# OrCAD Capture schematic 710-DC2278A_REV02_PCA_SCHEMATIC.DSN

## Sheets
1 PAGE4
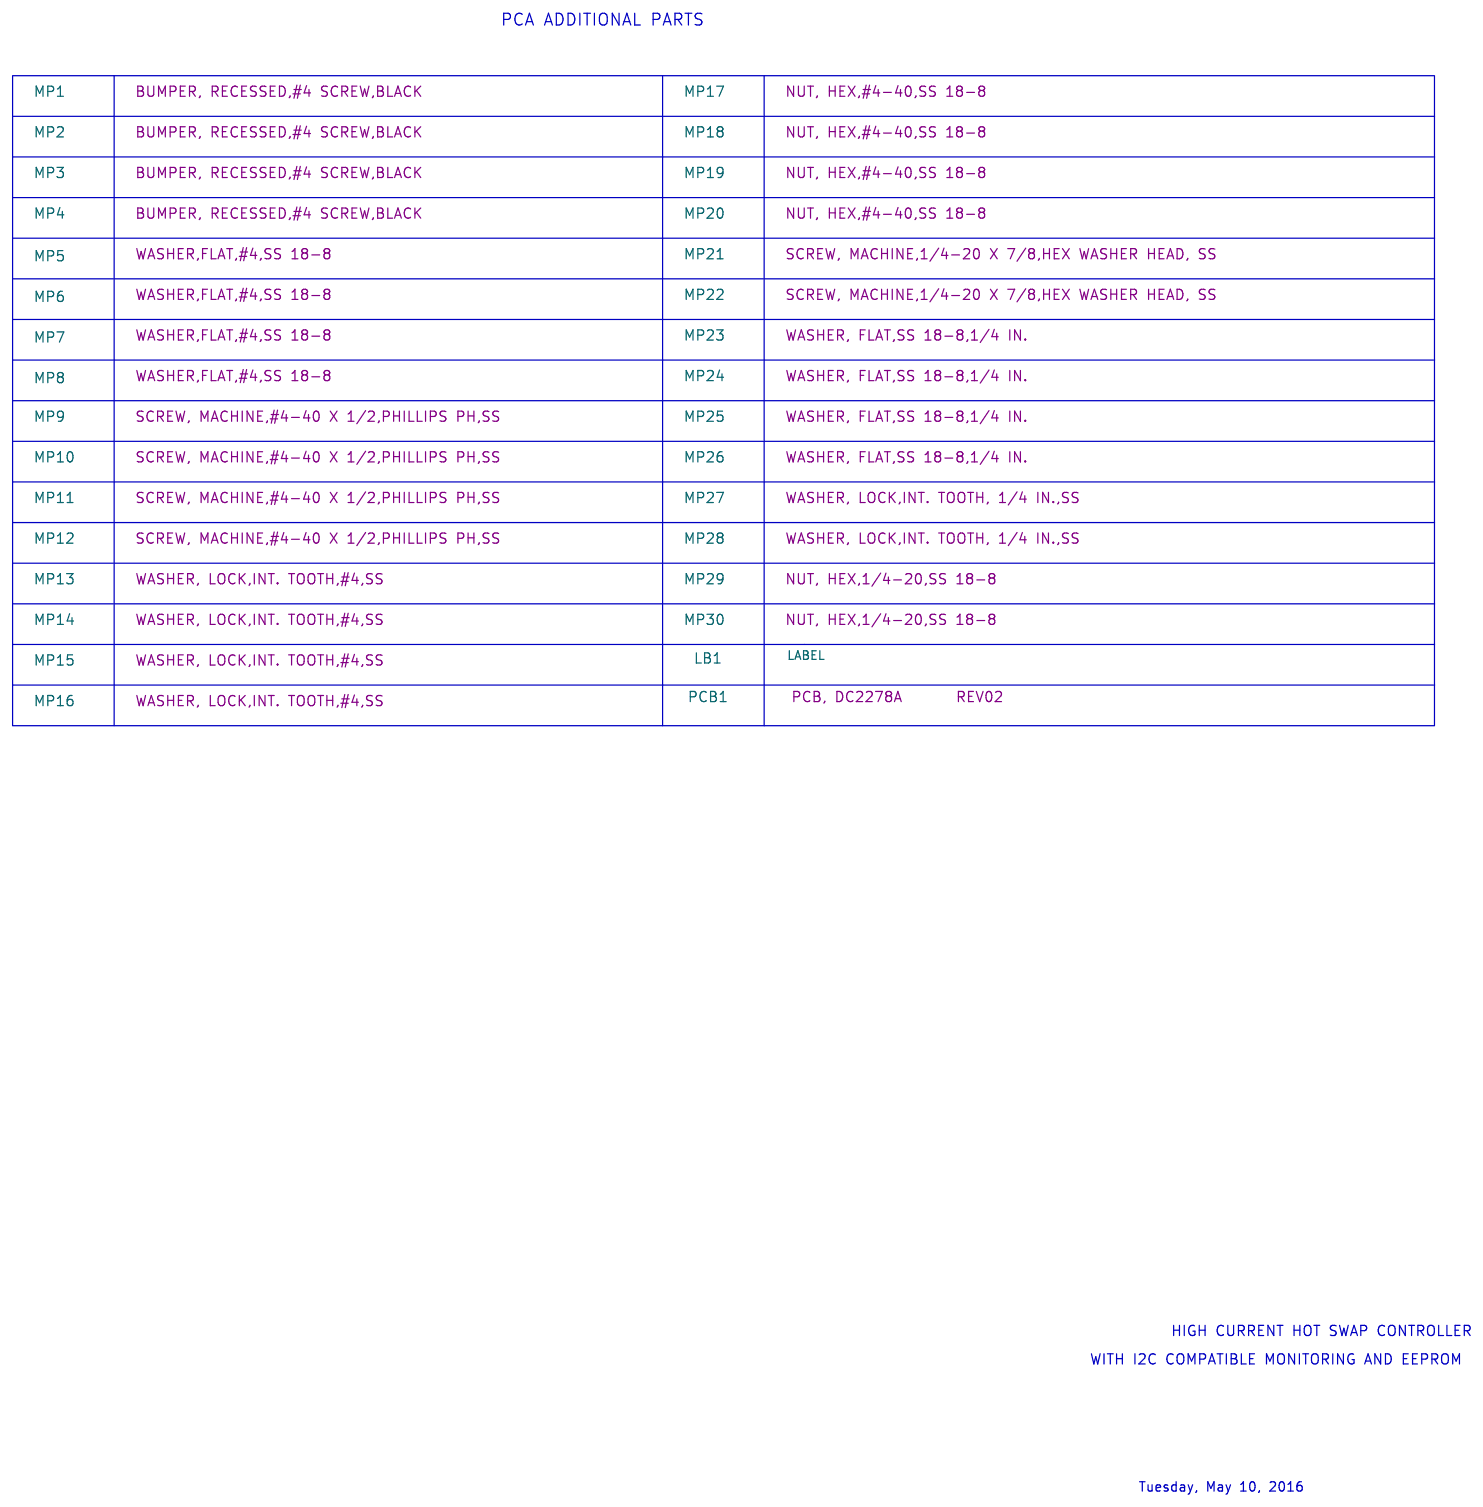
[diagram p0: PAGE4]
2 PAGE1: size Custom; note: HIGH CURRENT HOT SWAP CONTROLLER WITH I2C COMPATIBLE MONITORING AND EEPROM
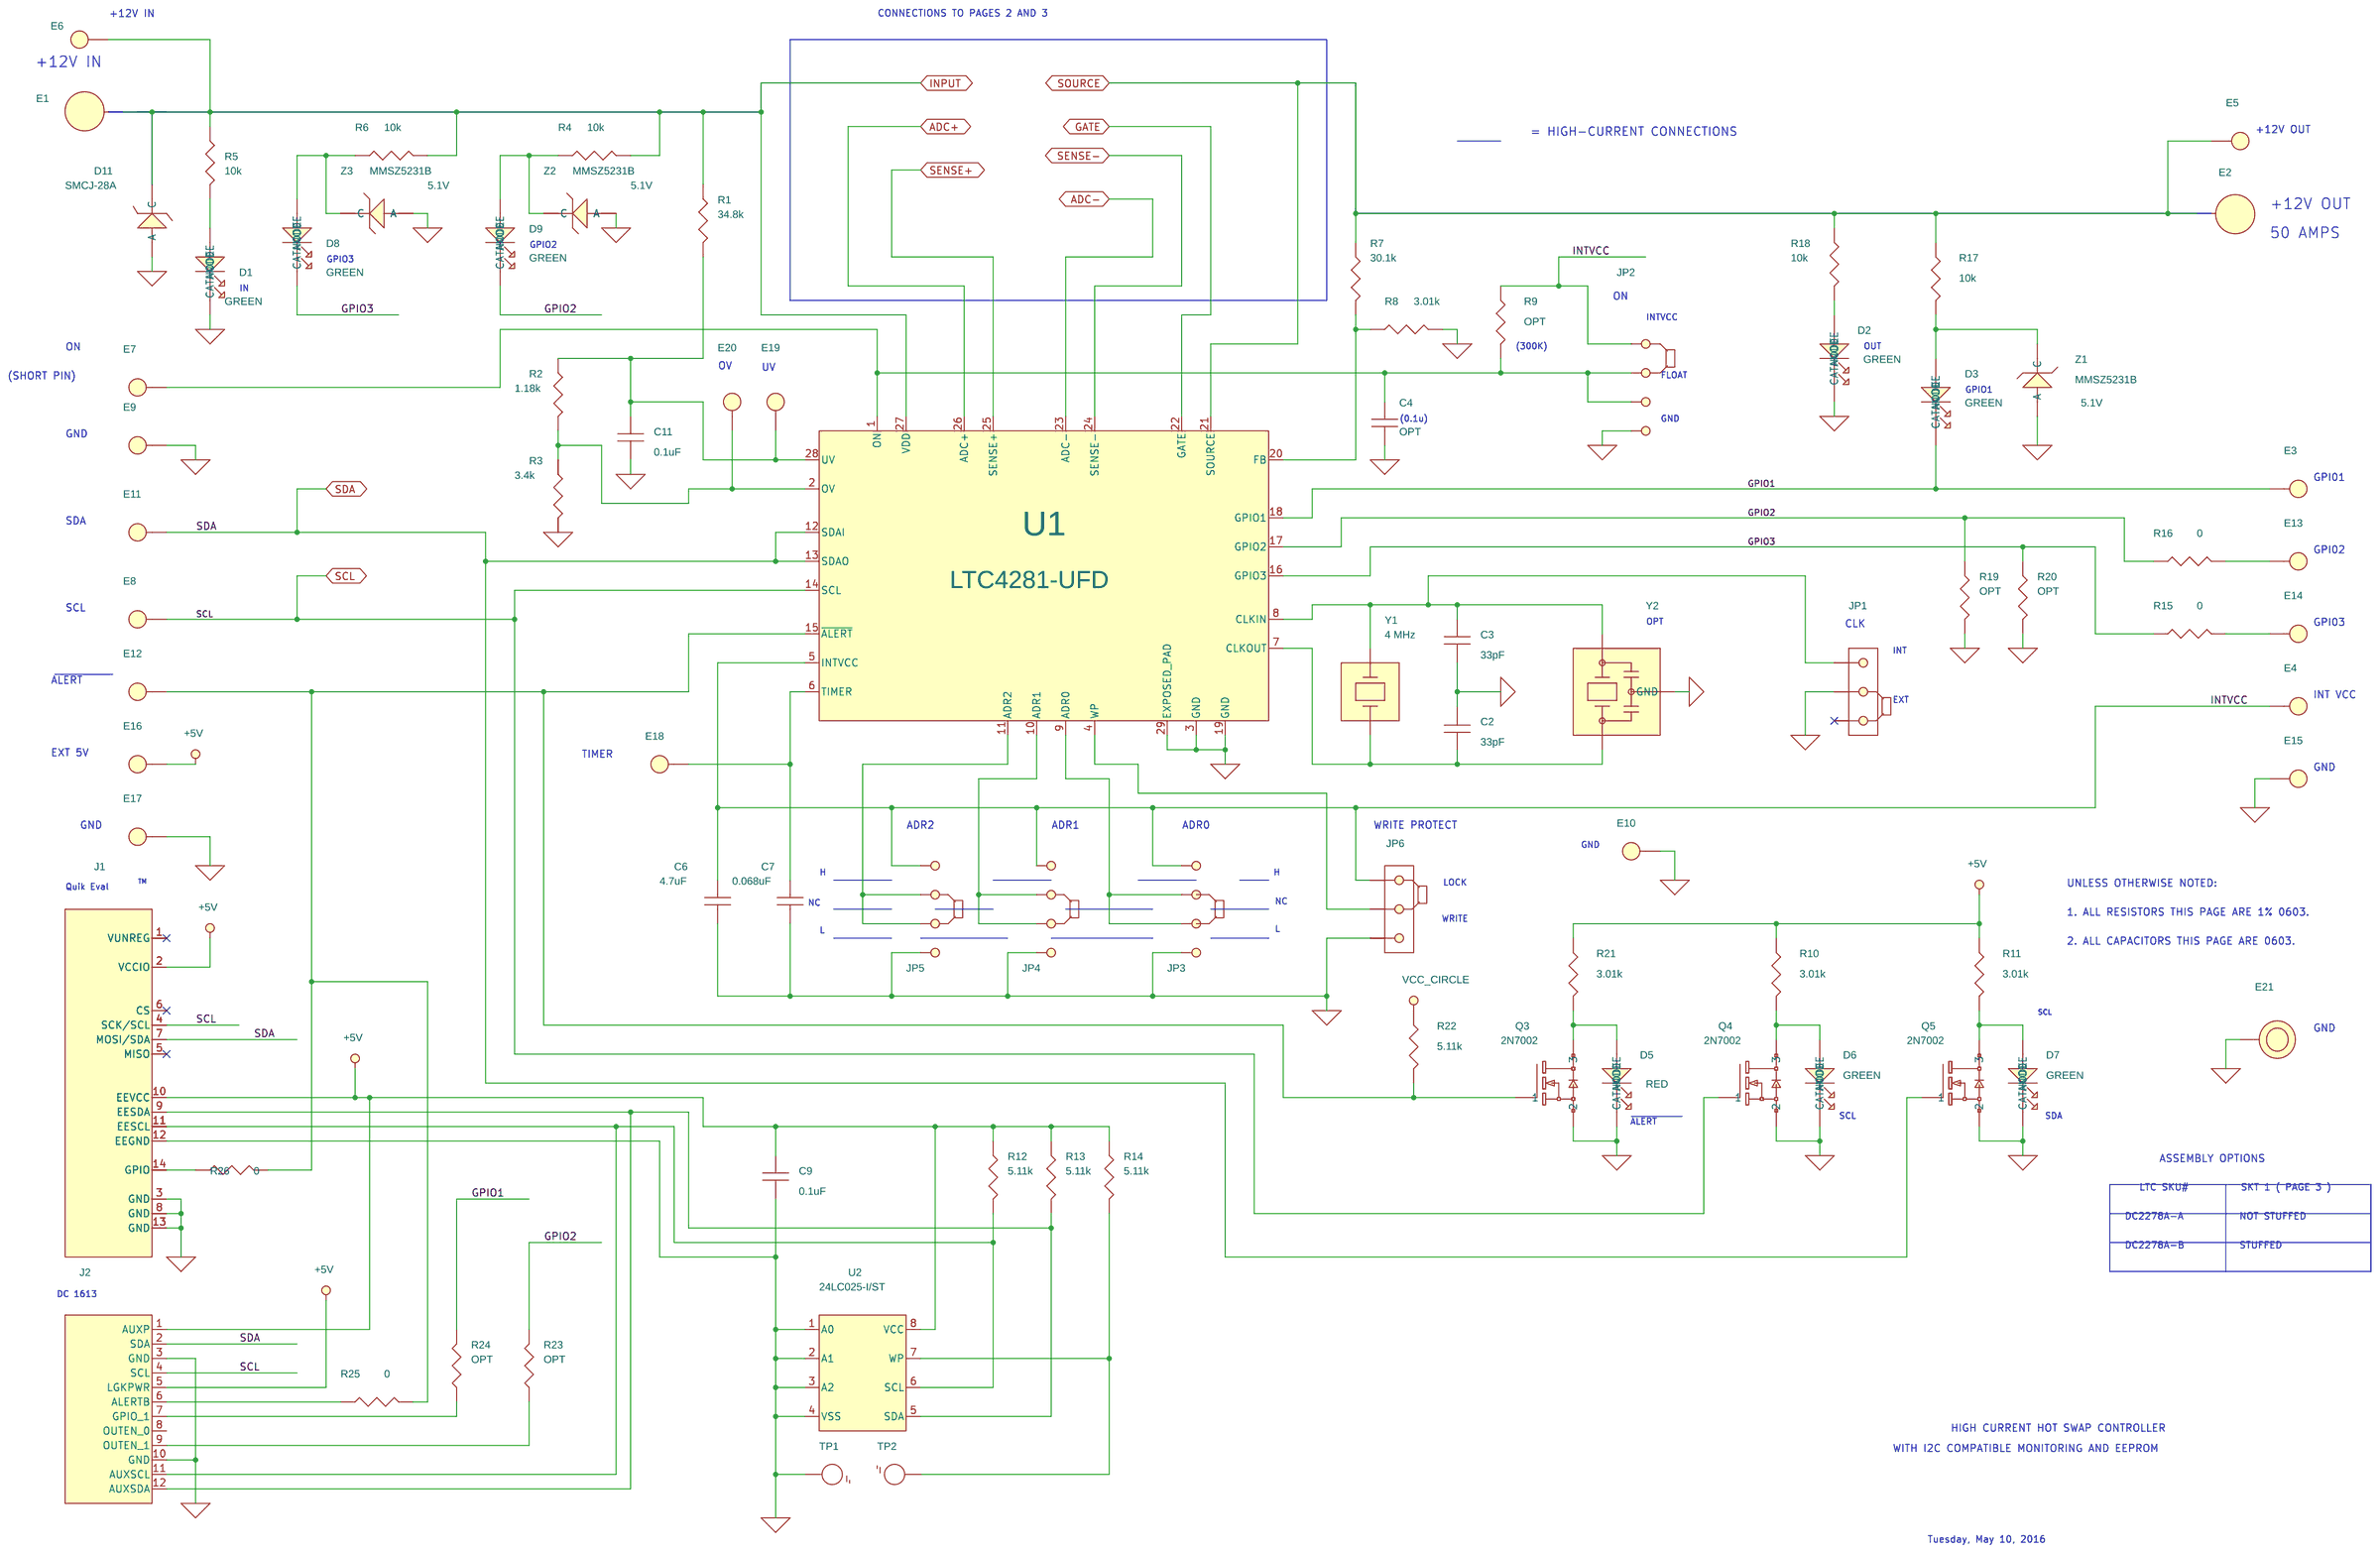
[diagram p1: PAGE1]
3 PAGE2: size Custom
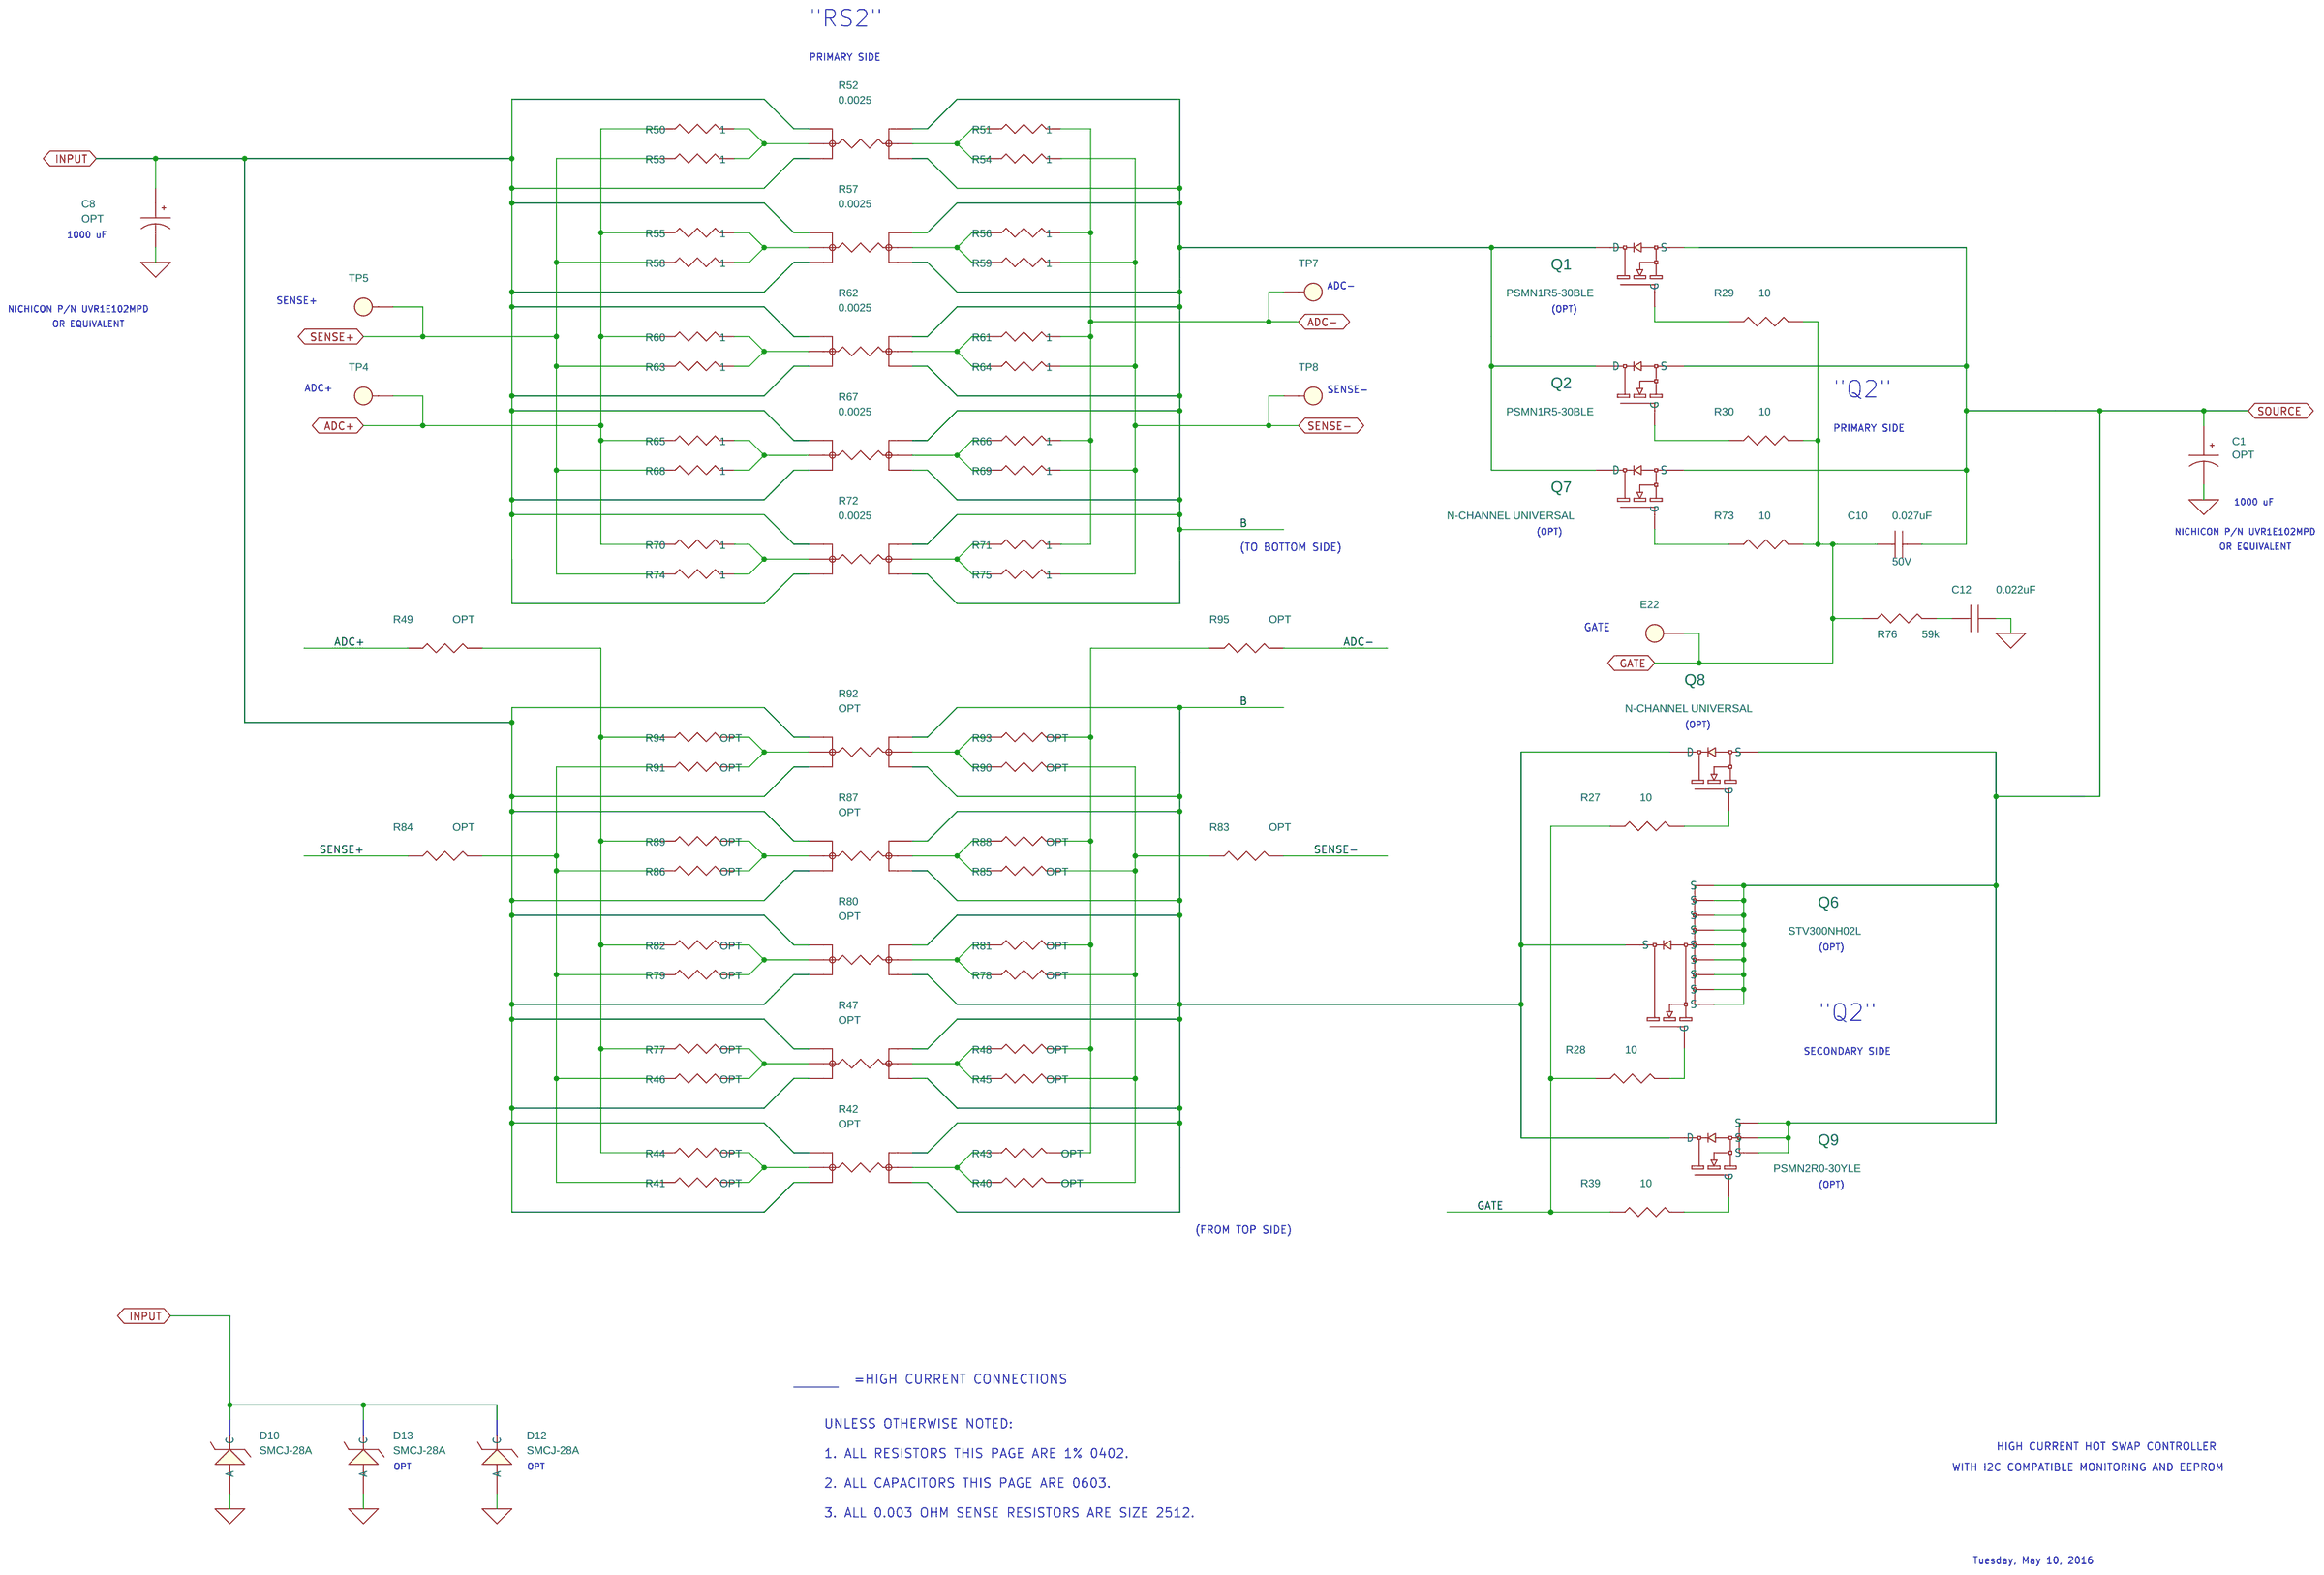
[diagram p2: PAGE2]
4 PAGE3: size Custom
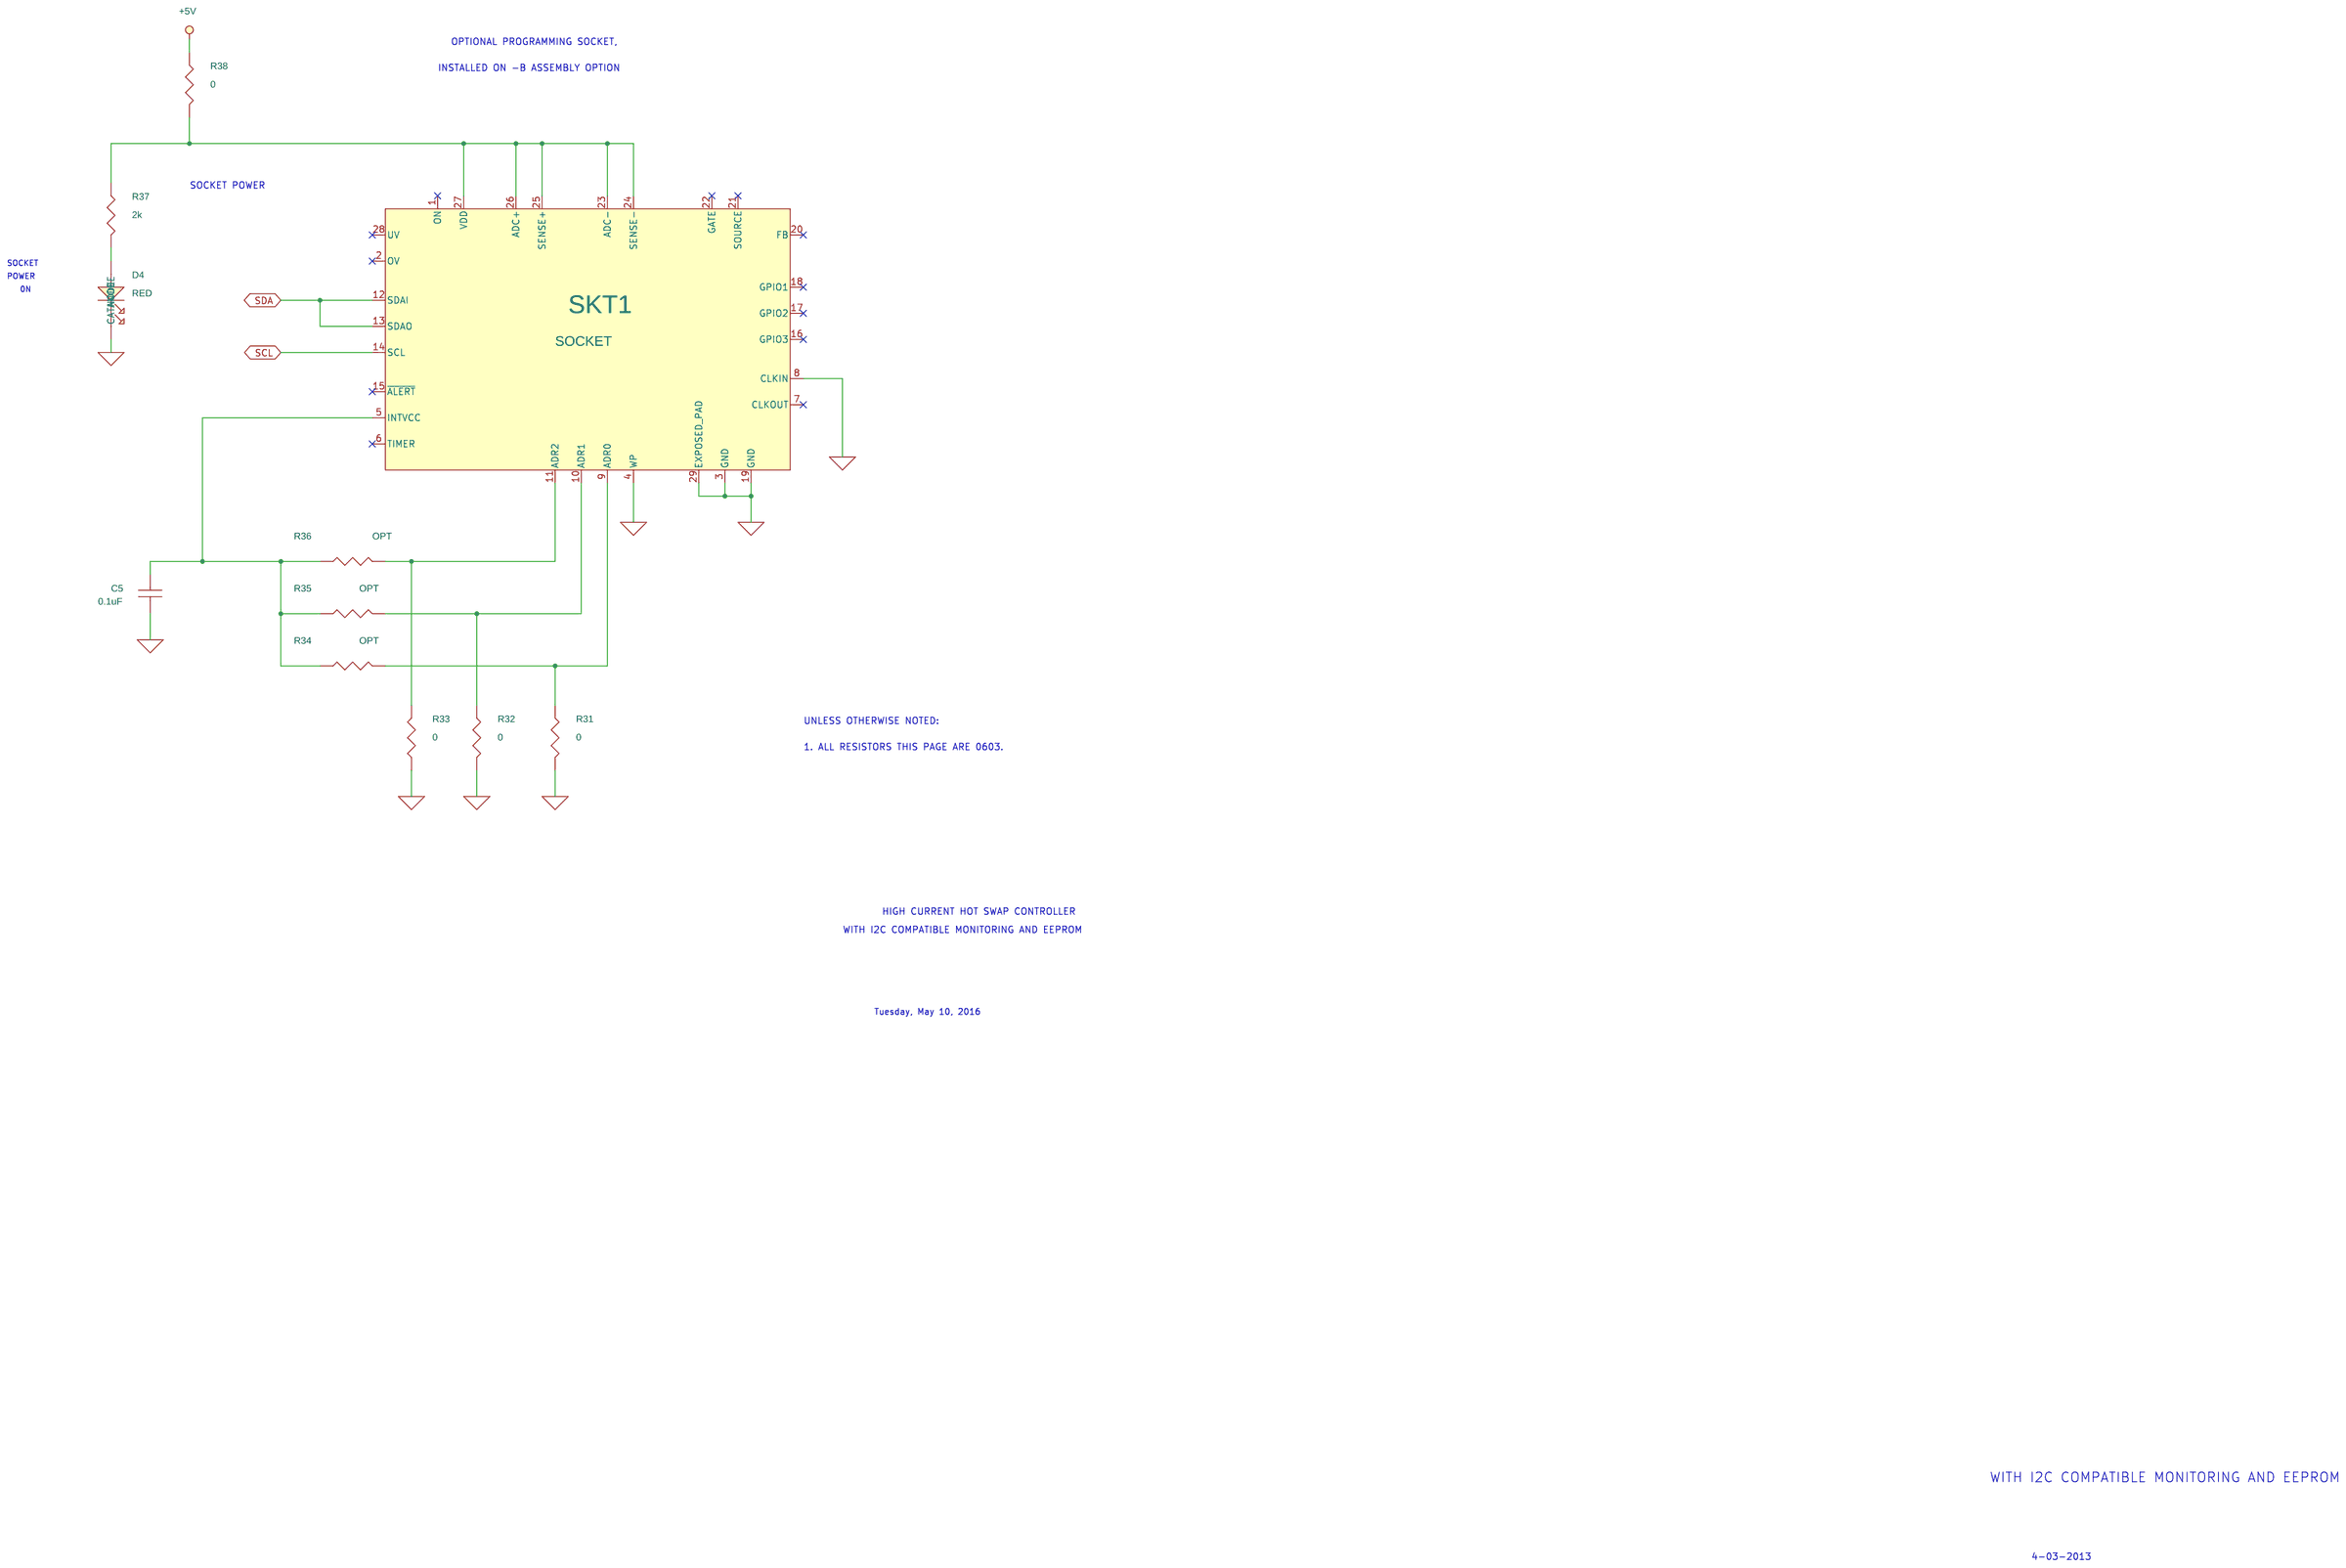
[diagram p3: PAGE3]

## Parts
sheet PAGE1
C2  33pF  [CC0603N]
C3  33pF  [CC0603N]
C4  OPT  [CC0603N]
C6  4.7uF  [CC0603N]
C7  0.068uF  [CC0603N]
C9  0.1uF  [CC0603N]
C11  0.1uF  [CC0603N]
D1  GREEN  [WURTH_LED_0805]
D2  GREEN  [WURTH_LED_0805]
D3  GREEN  [WURTH_LED_0805]
D5  RED  [LED_0805]
D6  GREEN  [WURTH_LED_0805]
D7  GREEN  [WURTH_LED_0805]
D8  GREEN  [WURTH_LED_0805]
D9  GREEN  [WURTH_LED_0805]
D11  SMCJ-28A  [DIODESINC-SMC]
E1  LUG, TONGUE  [CBA70-14-CY]
E2  LUG, TONGUE  [CBA70-14-CY]
E3  TEST POINT  [MILLMAX2308]
E4  TEST POINT  [MILLMAX2308]
E5  TEST POINT  [MILLMAX2308]
E6  TEST POINT  [MILLMAX2308]
E7  TEST POINT  [MILLMAX2308]
E8  TEST POINT  [MILLMAX2308]
E9  TEST POINT  [MILLMAX2308]
E10  TEST POINT  [MILLMAX2308]
E11  TEST POINT  [MILLMAX2308]
E12  TEST POINT  [MILLMAX2308]
E13  TEST POINT  [MILLMAX2308]
E14  TEST POINT  [MILLMAX2308]
E15  TEST POINT  [MILLMAX2308]
E16  TEST POINT  [MILLMAX2308]
E17  TEST POINT  [MILLMAX2308]
E18  TEST POINT  [MILLMAX2308]
E19  TEST POINT  [MILLMAX2308]
E20  TEST POINT  [MILLMAX2308]
E21  BANANA JACK  [KEY-575-4]
J1  HDR.  [HD2X7-079-MOLEX]
J2  HDR., SHROUDED  [HD2X6-079-MOLEX]
JP1  HDR.  [JP3X1/079]
JP2  HDR.  [JP4X1/079]
JP3  HDR.  [JP4X1/079]
JP4  HDR.  [JP4X1/079]
JP5  HDR.  [JP4X1/079]
JP6  HDR.  [JP3X1/079]
Q3  2N7002  [SOT23-3N]
Q4  2N7002  [SOT23-3N]
Q5  2N7002  [SOT23-3N]
R1  34.8k  [CR0603N]
R2  1.18k  [CR0603N]
R3  3.4k  [CR0603N]
R4  10k  [CR1206N]
R5  10k  [CR1206N]
R6  10k  [CR1206N]
R7  30.1k  [CR0603N]
R8  3.01k  [CR0603N]
R9  OPT  [CR0603N]
R10  3.01k  [CR0603N]
R11  3.01k  [CR0603N]
R12  5.11k  [CR0603N]
R13  5.11k  [CR0603N]
R14  5.11k  [CR0603N]
R15  0  [CR0603N]
R16  0  [CR0603N]
R17  10k  [CR1206N]
R18  10k  [CR1206N]
R19  OPT  [CR0603N]
R20  OPT  [CR0603N]
R21  3.01k  [CR0603N]
R22  5.11k  [CR0603N]
R23  OPT  [CR0603N]
R24  OPT  [CR0603N]
R25  0  [CR0603N]
R26  0  [CR0603N]
TP1  TEST PAD  [PADSTYLE6]
TP2  TEST PAD  [PADSTYLE6]
U1  LTC4281-UFD  [LTC-UFD-28-1712]
U2  24LC025-I/ST  [MICROCHIP-TSSOP-8]
XJP4  SHUNT
XJP5  SHUNT
XJP6  SHUNT
XJP10  SHUNT
XJP11  SHUNT
XJP12  SHUNT
Y1  4 MHz  [ABRACON-ABLS]
Y2  4 Mhz  [MURATA-CSTCR_G]
Z1  MMSZ5231B  [SOD-123N]
Z2  MMSZ5231B  [SOD-123N]
Z3  MMSZ5231B  [SOD-123N]
sheet PAGE2
C1  OPT  [SUNCON_HVH_6.3X4.5]
C8  OPT  [SUNCON_HVH_6.3X4.5]
C10  0.027uF  [CC0603N]
C12  0.022uF  [CC0805N]
D10  SMCJ-28A  [DIODESINC-SMC]
D12  SMCJ-28A  [DIODESINC-SMC]
D13  SMCJ-28A  [DIODESINC-SMC]
E22  TEST POINT  [MILLMAX2308]
Q1  PSMN1R5-30BLE  [NXP-D2PAK]
Q2  PSMN1R5-30BLE  [NXP-D2PAK]
Q6  STV300NH02L  [STV300NH02L]
Q7  N-CHANNEL UNIVERSAL  [UNI-POWERFET]
Q8  N-CHANNEL UNIVERSAL  [UNI-POWERFET]
Q9  PSMN2R0-30YLE  [SOT-669]
R27  10  [CR0603N]
R28  10  [CR0603N]
R29  10  [CR0603N]
R30  10  [CR0603N]
R39  10  [CR0603N]
R40  OPT  [CR0402N]
R41  OPT  [CR0402N]
R42  OPT  [RSENSE-2512-6PIN]
R43  OPT  [CR0402N]
R44  OPT  [CR0402N]
R45  OPT  [CR0402N]
R46  OPT  [CR0402N]
R47  OPT  [RSENSE-2512-6PIN]
R48  OPT  [CR0402N]
R49  OPT  [CR0402N]
R50  1  [CR0402N]
R51  1  [CR0402N]
R52  0.0025  [RSENSE-2512-6PIN]
R53  1  [CR0402N]
R54  1  [CR0402N]
R55  1  [CR0402N]
R56  1  [CR0402N]
R57  0.0025  [RSENSE-2512-6PIN]
R58  1  [CR0402N]
R59  1  [CR0402N]
R60  1  [CR0402N]
R61  1  [CR0402N]
R62  0.0025  [RSENSE-2512-6PIN]
R63  1  [CR0402N]
R64  1  [CR0402N]
R65  1  [CR0402N]
R66  1  [CR0402N]
R67  0.0025  [RSENSE-2512-6PIN]
R68  1  [CR0402N]
R69  1  [CR0402N]
R70  1  [CR0402N]
R71  1  [CR0402N]
R72  0.0025  [RSENSE-2512-6PIN]
R73  10  [CR0603N]
R74  1  [CR0402N]
R75  1  [CR0402N]
R76  59k  [CR0603N]
R77  OPT  [CR0402N]
R78  OPT  [CR0402N]
R79  OPT  [CR0402N]
R80  OPT  [RSENSE-2512-6PIN]
R81  OPT  [CR0402N]
R82  OPT  [CR0402N]
R83  OPT  [CR0402N]
R84  OPT  [CR0402N]
R85  OPT  [CR0402N]
R86  OPT  [CR0402N]
R87  OPT  [RSENSE-2512-6PIN]
R88  OPT  [CR0402N]
R89  OPT  [CR0402N]
R90  OPT  [CR0402N]
R91  OPT  [CR0402N]
R92  OPT  [RSENSE-2512-6PIN]
R93  OPT  [CR0402N]
R94  OPT  [CR0402N]
R95  OPT  [CR0402N]
TP4  TEST PAD  [PADSTYLE3]
TP5  TEST PAD  [PADSTYLE3]
TP7  TEST PAD  [PADSTYLE3]
TP8  TEST PAD  [PADSTYLE3]
sheet PAGE3
C5  0.1uF  [CC0603N]
D4  RED  [LED_0805]
R31  0  [CR0603N]
R32  0  [CR0603N]
R33  0  [CR0603N]
R34  OPT  [CR0603N]
R35  OPT  [CR0603N]
R36  OPT  [CR0603N]
R37  2k  [CR0603N]
R38  0  [CR0603N]
SKT1  SOCKET  [28QN50S25040]
sheet PAGE4
LB1  LABEL  [895-0154_REV01]
MP1  BUMPER, RECESSED
MP2  BUMPER, RECESSED
MP3  BUMPER, RECESSED
MP4  BUMPER, RECESSED
MP5  WASHER
MP6  WASHER
MP7  WASHER
MP8  WASHER
MP9  SCREW, MACHINE
MP10  SCREW, MACHINE
MP11  SCREW, MACHINE
MP12  SCREW, MACHINE
MP13  WASHER, LOCK
MP14  WASHER, LOCK
MP15  WASHER, LOCK
MP16  WASHER, LOCK
MP17  NUT, HEX
MP18  NUT, HEX
MP19  NUT, HEX
MP20  NUT, HEX
MP21  SCREW, MACHINE
MP22  SCREW, MACHINE
MP23  WASHER, FLAT
MP24  WASHER, FLAT
MP25  WASHER, FLAT
MP26  WASHER, FLAT
MP27  WASHER, LOCK
MP28  WASHER, LOCK
MP29  NUT, HEX
MP30  NUT, HEX
PCB1  PCB, DC2278A

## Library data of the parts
C2 C3 = CAP: CAP.,33pF,X7R,16V,5%,0603; CLASS: DISCRETE; Dielectric Type: X7R; Manufacturer: AVX; Manufacturer PN: 0603YC330JAT2A; PART_NUMBER: 150-2014; Package Size: 0603; Package Type: SMD; Rated Voltage: 16V; Tolerance: 5%
C4 = CAP: CAP., OPTION, 0603; CLASS: DISCRETE; FPLIST: CC0603N,CC0603L,CC0603M; Manufacturer: OPTION; Manufacturer PN: OPTION; PART_NUMBER: OPT-0014; Package Size: 0603; Package Type: SMD
C6 = CAP: CAP.,4.7uF,X5R,16V,10%,0603; CLASS: DISCRETE; Dielectric Type: X5R; Manufacturer: TDK; Manufacturer PN: C1608X5R1C475K080AC; PART_NUMBER: 150-3182; Package Size: 0603; Rated Voltage: 16V; Tolerance: 10%
C7 = CAP: CAP.,0.068uF,X7R,16V,10%,0603; CLASS: DISCRETE; Dielectric Type: X7R; FPLIST: CC0603N,CC0603L,CC0603M; Manufacturer: AVX; Manufacturer PN: 0603YC683KAT2A; PART_NUMBER: 150-0017; Package Size: 0603; Rated Voltage: 16V; Tolerance: 10%
C5 C9 = CAP: CAP.,0.1uF,X7R,16V,10%,0603; CLASS: DISCRETE; Dielectric Type: X7R; Manufacturer: AVX; Manufacturer PN: 0603YC104KAT2A; PART_NUMBER: 150-0164; Package Size: 0603; Package Type: SMD; Rated Voltage: 16V; Tolerance: 10%
C11 = CAP: CAP.,0.1uF,X7R,25V,20%,0603; CLASS: DISCRETE; Dielectric Type: X7R; Manufacturer: TDK; Manufacturer PN: C1608X7R1E104M080AA; PART_NUMBER: 150-3402; Package Size: 0603; Package Type: SMD; Rated Voltage: 25V; Tolerance: 20%
D1-D3 D6-D9 = LED: LED,GREEN,WATERCLEAR,0805; CLASS: DISCRETE; Manufacturer: WURTH ELEKTRONIK; Manufacturer PN: 150080GS75000; PART_NUMBER: 270-0063; Package Size: 0805
D4 D5 = LED: LED,RED,WATER CLEAR,2 PIN SMD; CLASS: DISCRETE; Manufacturer: LITE-ON TECHNOLOGY CORP; Manufacturer PN: LTST-C170EKT; PART_NUMBER: 270-0069; Package Size: 0805
D10-D13 = DIODE_TVS_B: DIODE,TVS,28V,1500W,SMC; BOM Notes: D12,D13 OPT; CLASS: DISCRETE; Manufacturer: DIODES INC.; Manufacturer PN: SMCJ28A-13-F; PART_NUMBER: 210-0182; Package Size: SMC; Rated Voltage: 28V
E1 E2 = TONGUE_LUG: LUG, TONGUE,OFFSET FLOATING,ONE HOLE; CLASS: IO; Manufacturer: PENCOM; Manufacturer PN: EL1664; PART_NUMBER: 769-0008
E3-E20 E22 = TEST_POINT_.156_MILL-MAX_2308: TEST POINT,TURRET,0.064" MTG. HOLE,0.125" THICK PCB; CLASS: IO; Manufacturer PN: 2308-4-00-80-00-00-07-0; PART_NUMBER: 260-0008
E21 = BANANA_KEYSTONE-575-4: CONN.,BANANA JACK,FEMALE,THT,NON-INSULATED, SWAGE; CLASS: IO; Manufacturer PN: 575-4; PART_NUMBER: 250-0428
J1 = CONN_2X7_.079_MOLEX_RIBBON_A: CONN.,HDR.,MALE,2x7,2mm,THT, VERT,SHROUDED; CLASS: IO; Manufacturer PN: 87831-1420; PART_NUMBER: 250-0403
J2 = CONN._FCI_12_POS_2MM: CONN.,HDR., SHROUDED,2X6,2mm,THT, VERT; CLASS: IO; Manufacturer PN: 98414-G06-12ULF; PART_NUMBER: 250-0433
JP1 JP6 = HDR3X1_C: CONN.,HDR.,MALE,1X3,2mm,THT, STRT; CLASS: IO; Manufacturer PN: TMM-103-02-L-S; PART_NUMBER: 250-0422
JP2-JP5 = 4_PIN_HEADER_.079_SINGLE_ROW_C: CONN.,HDR.,MALE,1X4,2mm,THT, STRT; CLASS: IO; Manufacturer: SAMTEC; Manufacturer PN: TMM-104-02-L-S; PART_NUMBER: 250-0441
Q3-Q5 = 2N7002_SOT-23: XSTR.,MOSFET N-CH,60V,300mA,SOT-23; CLASS: DISCRETE; Manufacturer: VISHAY; Manufacturer PN: 2N7002K-T1-GE3; PART_NUMBER: 240-0125; Package Size: SOT-23; Package Type: SOT-23
R1 = RES: RES.,34.8k OHMS,1%,1/10W,0603; CLASS: DISCRETE; Manufacturer: VISHAY; Manufacturer PN: CRCW060334K8FKEA; PART_NUMBER: 100-2669; Package Size: 0603; Rated Power: 1/10W; Temperature Coefficient: 100ppm/C; Tolerance: 1%
R2 = RES: RES.,1.18k OHMS,1%,1/10W,0603; CLASS: DISCRETE; Manufacturer: YAGEO; Manufacturer PN: RC0603FR-071K18L; PART_NUMBER: 100-2015; Package Size: 0603; Rated Power: 1/10W; Temperature Coefficient: +/-100 PPM; Tolerance: 1%
R3 = RES: RES.,3.4k OHMS,1%,1/10W,0603; CLASS: DISCRETE; Manufacturer: NIC; Manufacturer PN: NRC06F3741TRF; PART_NUMBER: 100-2782; Package Size: 0603; Rated Power: 1/10W; Temperature Coefficient: 100ppm/C; Tolerance: 1%
R4-R6 R17 R18 = RES: RES.,10k OHMS,5%,1/4W,1206; CLASS: DISCRETE; Manufacturer: PANASONIC; Manufacturer PN: ERJ8GEYJ103V; PART_NUMBER: 100-0317; Package Size: 1206; Rated Power: 1/4W; Temperature Coefficient: 200ppm; Tolerance: 5%
R7 = RES: RES.,30.1k OHMS,1%,1/10W,0603; CLASS: DISCRETE; Manufacturer: PANASONIC; Manufacturer PN: ERJ3EKF3012V; PART_NUMBER: 100-2524; Package Size: 0603; Rated Power: 1/10W; Temperature Coefficient: 100ppm/C; Tolerance: 1%
R8 R10 R11 R21 = RES: RES.,3.01k OHMS,1%,1/10W,0603; CLASS: DISCRETE; Manufacturer: VISHAY; Manufacturer PN: CRCW06033K01FKEA; PART_NUMBER: 100-2477; Package Size: 0603; Rated Power: 1/10W; Temperature Coefficient: 100ppm/C; Tolerance: 1%
R9 R19 R20 R23 R24 R34-R36 = RES: RES., OPTION, 0603; CLASS: DISCRETE; FPLIST: CR0603N,CR0603L,CR0603M; Manufacturer: OPTION; Manufacturer PN: OPTION; PART_NUMBER: OPT-0018; Package Size: 0603
R12-R14 R22 = RES: RES.,5.11k OHMS,1%,1/10W,0603; CLASS: DISCRETE; Manufacturer: PANASONIC; Manufacturer PN: ERJ3EKF5111V; PART_NUMBER: 100-2603; Package Size: 0603; Rated Power: 1/10W; Temperature Coefficient: 100ppm/C; Tolerance: 1%
R15 R16 R25 R26 R31-R33 R38 = RES: RES.,0 OHM,1/10W,0603; CLASS: DISCRETE; Manufacturer: VISHAY; Manufacturer PN: CRCW06030000Z0EA; PART_NUMBER: 100-0009; Package Size: 0603; Rated Power: 1/10W
TP1 TP2 = TESTPOINT_FILLED_CIRCLE: TESTPOINT, PCB COPPER FEATURE; CLASS: IO; FPLIST: PADSTYLE1,PADSTYLE2,PADSTYLE3,PADSTYLE4,PADSTYLE5,PADSTYLE6,PADSTYLE7,PADSTYLE8; Manufacturer: N/A; Manufacturer PN: N/A; PART_NUMBER: PCBPADS-1
U1 = LTC4281-UFD: IC,HI-CURRENT HOT SWAP CONTROLLER,QFN; CLASS: IC; Manufacturer: LINEAR TECHNOLOGY; Manufacturer PN: LTC4281IUFD#PBF; PART_NUMBER: LTC4281IUFD#PBF; Package Size: LTC-UFD28; Package Type: QFN
U2 = 24LC025-I_ST_TSSOP-8: IC, MEMORY,EEPROM,2K-bit, 400kHz,TSSOP-8; CLASS: IC; Manufacturer: Microchip; PART_NUMBER: 380-0087; Package Size: TSSOP-8; Package Type: TSSOP-8
XJP4-XJP6 XJP10-XJP12 = SHUNT_2MM: CONN.,SHUNT,FEMALE,2 POS,2mm; CLASS: IO; Manufacturer PN: 2SN-BK-G; PART_NUMBER: 250-0419
Y1 = XTAL_4MHZ_ABLS: CRYSTAL,4 MHz,18pF,+/-50ppm,11.4mm x 4.7mm, 2Pad SMD; CLASS: DISCRETE; Frequency Stability: +/-50ppm; Manufacturer: ABRACON CORPORATION; Manufacturer PN: ABLS-4.000MHZ-B4-T; PART_NUMBER: 340-0072
Y2 = RESONATOR_MURATA: RESONATOR, 4Mhz, SMT, OPTION; CLASS: DISCRETE; Manufacturer: MURATA; Manufacturer PN: CSTCR4M00G53-R0 (OPTION); PART_NUMBER: OPT-0010
Z1-Z3 = ZENER: DIODE,ZENER,5.1V,500mW,SOD-123; CLASS: DISCRETE; Manufacturer: FAIRCHILD; PART_NUMBER: 210-0183; Package Size: SOD-123; Rated Voltage: 5.1V
C1 C8 = CAP_P: CAP., OPTION, ALUM. ELECT., SMD; CLASS: DISCRETE; Dielectric Type: ALUM. ELECTROLYTIC; FPLIST: CAP-HVH-6.3X4.5,SUNCON-8X10.2,SUNCON-6.3X5.4,CAPRD10H20LS5; Manufacturer: OPTION; Manufacturer PN: OPTION; PART_NUMBER: OPT-0011; Package Size: SMT; Package Type: SMD
C10 = CAP: CAP.,0.027uF,X7R,50V,10%,0603; CLASS: DISCRETE; Dielectric Type: X7R; Manufacturer: AVX; Manufacturer PN: 06035C273KAT2A; PART_NUMBER: 150-2015; Package Size: 0603; Package Type: Surface Mount, MLCC; Rated Voltage: 50V; Temperature Coefficient: X7R; Tolerance: 10%
C12 = CAP: CAP.,0.022uF,X7R,50V,5%,0805; CLASS: DISCRETE; Dielectric Type: X7R; FPLIST: CC0805N,CC0805L,CC0805M; Manufacturer: Kemet; Manufacturer PN: C0805C223J5RACTU; PART_NUMBER: 150-2016; Package Size: 0805; Package Type: Surface Mount, MLCC; Rated Voltage: 50V; Tolerance: 5%
Q1 Q2 = PSMN1R5-30BLE: XSTR.,MOSFET N-CHAN,30V,120A,D2PAK; CLASS: DISCRETE; Manufacturer: NXP SEMICONDUCTORS; PART_NUMBER: 240-0182; Package Size: D2PAK; Package Type: D2PAK
Q6 = STV300NH02L: TRANSISTOR, MOSFET,N-CH., SO-10, OPTIONAL; CLASS: DISCRETE; Manufacturer: ST MICROELECTRONICS; PART_NUMBER: OPT-0041; Part Number: OPTION
Q7 Q8 = N-CH_UNIVERSAL: MOSFET, N-CH, OPTION; CLASS: DISCRETE; Manufacturer: OPTION; Manufacturer PN: OPTION; PART_NUMBER: OPT-0042
Q9 = PSMN2R0-30YLE: TRANSISTOR, MOSFET, N-CH., SOT-669- OPTIONAL; CLASS: DISCRETE; Manufacturer: NXP; PART_NUMBER: OPT-0040; Package Size: SOT669; Package Type: SMD
R27-R30 R39 R73 = RES: RES.,10 OHMS,5%,1/10W,0603; CLASS: DISCRETE; Manufacturer: PANASONIC; Manufacturer PN: ERJ3GEYJ100V; PART_NUMBER: 100-2058; Package Size: 0603; Rated Power: 1/10W; Temperature Coefficient: 200ppm/C; Tolerance: 5%
R40 R41 R43-R46 R48 R49 R77-R79 R81-R86 R88-R91 R93-R95 = RES: RES., OPTION, 0402; CLASS: DISCRETE; FPLIST: CR0402N,CR0402L,CR0402M; Manufacturer: OPTION; Manufacturer PN: OPTION; PART_NUMBER: OPT-0017; Package Size: 0402
R42 R47 R80 R87 R92 = RES_6PIN: RES., OPTION, 2512; CLASS: DISCRETE; Manufacturer: Optek Technology (TT electronics); Manufacturer PN: LRMAT2512-R003FT4; PART_NUMBER: OPT-0008; Package Size: 2512; Rated Power: 2W
R50 R51 R53-R56 R58-R61 R63-R66 R68-R71 R74 R75 = RES: RES.,1 OHM,1%,1/16W,0402; CLASS: DISCRETE; Manufacturer: VISHAY; Manufacturer PN: CRCW04021R00FKED; PART_NUMBER: 100-0241; Package Size: 0402; Rated Power: 1/16W; Temperature Coefficient: 100ppm; Tolerance: 1%
R52 R57 R62 R67 R72 = RES_6PIN: RES.,METAL ELEMENT,0.0025 OHMS,1%,3W,2512; CLASS: DISCRETE; Manufacturer: TT ELECTRONICS; Manufacturer PN: ULRG3-2512-R0025-F-LF-SLT; PART_NUMBER: 100-2120; Package Size: 2512; Rated Power: 3W; Temperature Coefficient: +/- 50PPM
R76 = RES: RES.,59k OHMS,1%,1/10W,0603; CLASS: DISCRETE; FPLIST: CR0603N,CR0603L,CR0603M; Manufacturer: VISHAY; Manufacturer PN: CRCW060359K0FKEA; PART_NUMBER: 100-2121; Package Size: 0603; Rated Power: 1/10W; Temperature Coefficient: +/-100PPM; Tolerance: 1%
TP4 TP5 TP7 TP8 = PAD_STYLE_C: TESTPOINT, PCB COPPER FEATURE; CLASS: IO; FPLIST: PADSTYLE1,PADSTYLE2,PADSTYLE3,PADSTYLE4,PADSTYLE5,PADSTYLE6,PADSTYLE7,PADSTYLE8; Manufacturer: N/A; Manufacturer PN: N/A; PART_NUMBER: PCBPADS-1
R37 = RES: RES.,2k OHMS,1%,1/10W,0603; CLASS: DISCRETE; Manufacturer: NIC; Manufacturer PN: NRC06F2001TRF; PART_NUMBER: 100-2313; Package Size: 0603; Rated Power: 1/10W; Temperature Coefficient: 100ppm/C; Tolerance: 1%
SKT1 = LTC4281-UFD: CONN.,SOCKET,CLAMSHELL,28 LEAD,SMT,5x4mm QFN; CLASS: IC; Manufacturer: PLASTRONICS; PART_NUMBER: 250-0575
LB1 = BLANK_LABEL: LABEL SPEC, DEMO BOARD SERIAL NUMBER; Manufacturer: BRADY; Manufacturer PN: THT-96-717-10; PART_NUMBER: 895-0154
MP1-MP4 = BLANK_PINLESS_MECHANICAL_PART: BUMPER, RECESSED,#4 SCREW,BLACK; CLASS: MECHANICAL PART; Manufacturer: KEYSTONE; Manufacturer PN: 727; PART_NUMBER: 763-0018
MP5-MP8 = BLANK_PINLESS_MECHANICAL_PART: WASHER,FLAT,#4,SS 18-8; CLASS: MECHANICAL PART; Manufacturer: PENCOM; Manufacturer PN: WA1021; PART_NUMBER: 762-0008
MP9-MP12 = BLANK_PINLESS_MECHANICAL_PART: SCREW, MACHINE,#4-40 X 1/2,PHILLIPS PH,SS; CLASS: MECHANICAL PART; Manufacturer: PENCOM; Manufacturer PN: SC3389; PART_NUMBER: 760-0065
MP13-MP16 = BLANK_PINLESS_MECHANICAL_PART: WASHER, LOCK,INT. TOOTH,#4,SS; CLASS: MECHANICAL PART; Manufacturer: PENCOM; Manufacturer PN: WA1196; PART_NUMBER: 762-0009
MP17-MP20 = BLANK_PINLESS_MECHANICAL_PART: NUT, HEX,#4-40,SS 18-8; CLASS: MECHANICAL PART; Manufacturer: PENCOM; Manufacturer PN: NU1043; PART_NUMBER: 761-0005
MP21 MP22 = BLANK_PINLESS_MECHANICAL_PART: SCREW, MACHINE,1/4-20 X 7/8,HEX WASHER HEAD, SS; CLASS: MECHANICAL PART; Manufacturer: PENCOM; Manufacturer PN: SE6037; PART_NUMBER: 760-0067
MP23-MP26 = BLANK_PINLESS_MECHANICAL_PART: WASHER, FLAT,SS 18-8,1/4 IN.; CLASS: MECHANICAL PART; Manufacturer: PENCOM; Manufacturer PN: WA3491; PART_NUMBER: 762-0012
MP27 MP28 = BLANK_PINLESS_MECHANICAL_PART: WASHER, LOCK,INT. TOOTH, 1/4 IN.,SS; CLASS: MECHANICAL PART; Manufacturer: PENCOM; Manufacturer PN: WA1374; PART_NUMBER: 762-0013
MP29 MP30 = BLANK_PINLESS_MECHANICAL_PART: NUT, HEX,1/4-20,SS 18-8; CLASS: MECHANICAL PART; Manufacturer: PENCOM; Manufacturer PN: NU1006; PART_NUMBER: 761-0007
PCB1 = BLANK_PCB_PART: BOM Notes: REV02; CLASS: PCB; Manufacturer: MAO BANG; Manufacturer PN: 600-DC2278A; PART_NUMBER: 600-DC2278A

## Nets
+5V: C9.1 E16.1(A) J1.2(VCCIO) J1.10(EEVCC) J2.1(AUXP) J2.5(LGKPWR) R10.1 R11.1 R12.1 R13.1 R14.1 R21.1 R22.1 R38.1 U2.8(VCC)
GND_SIGNAL: C1.2 C2.2 C3.2 C4.2 C5.2 C6.2 C7.2 C8.2 C9.2 C11.2 C12.1 D1.1(CATHODE) D2.1(CATHODE) D4.1(CATHODE) D5.1(CATHODE) D6.1(CATHODE) D7.1(CATHODE) D10.2(A) D11.2(A) D12.2(A) D13.2(A) E9.1(A) E10.1(A) E15.1(A) E17.1(A) E21.1 J1.3(GND) J1.8(GND) J1.12(EEGND) J1.13(GND) J2.3(GND) J2.10(GND) JP1.2 JP2.4 JP3.4 JP4.4 JP5.4 JP6.3 Q3.2 Q4.2 Q5.2 R3.2 R8.2 R19.2 R20.2 R31.2 R32.2 R33.2 SKT1.3(GND) SKT1.4(WP) SKT1.8(CLKIN) SKT1.19(GND) SKT1.29(EXPOSED_PAD) TP1.1 U1.3(GND) U1.19(GND) U1.29(EXPOSED_PAD) U2.1(A0) U2.2(A1) U2.3(A2) U2.4(VSS) Y2.2(GND) Z1.2(A) Z2.2(A) Z3.2(A)
ADC+: R49.1 R50.1 R55.1 R60.1 R65.1 R70.1 TP4.1 U1.26(ADC+)
ADC-: R51.2 R56.2 R61.2 R66.2 R71.2 R95.2 TP7.1 U1.23(ADC-)
B: Q1.4(D) Q2.4(D) Q6.11(S) Q7.3(D) Q8.3(D) Q9.5(D) R42.4 R42.6 R47.4 R47.6 R52.4 R52.6 R57.4 R57.6 R62.4 R62.6 R67.4 R67.6 R72.4 R72.6 R80.4 R80.6 R87.4 R87.6 R92.4 R92.6
GATE: C10.1 E22.1(A) R27.1 R28.1 R29.2 R30.2 R39.1 R73.2 R76.2 U1.22(GATE)
GPIO1: D3.1(CATHODE) E3.1(A) R24.2 U1.18(GPIO1)
GPIO2: D9.1(CATHODE) R16.1 R19.1 R23.2 U1.17(GPIO2)
GPIO3: D8.1(CATHODE) R15.1 R20.1 U1.16(GPIO3)
INPUT: C8.1 D10.1(C) D11.1(C) D12.1(C) D13.1(C) E1.1 E6.1(A) R1.1 R4.2 R5.1 R6.1 R42.3 R42.5 R47.3 R47.5 R52.3 R52.5 R57.3 R57.5 R62.3 R62.5 R67.3 R67.5 R72.3 R72.5 R80.3 R80.5 R87.3 R87.5 R92.3 R92.5 U1.27(VDD)
INTVCC: C6.1 E4.1(A) JP2.1 JP3.1 JP4.1 JP5.1 JP6.1 R9.1 U1.5(INTVCC)
SCL: E8.1(A) J1.4(SCK/SCL) J2.4(SCL) Q4.1 SKT1.14(SCL) U1.14(SCL)
SDA: E11.1(A) J1.7(MOSI/SDA) J2.2(SDA) Q5.1 SKT1.12(SDAI) SKT1.13(SDAO) U1.12(SDAI) U1.13(SDAO)
SENSE+: R53.1 R58.1 R63.1 R68.1 R74.1 R84.1 TP5.1 U1.25(SENSE+)
SENSE-: R54.2 R59.2 R64.2 R69.2 R75.2 R83.2 TP8.1 U1.24(SENSE-)
SOURCE: C1.1 C10.2 E2.1 E5.1(A) Q1.3(S) Q2.3(S) Q6.2(S) Q6.3(S) Q6.4(S) Q6.5(S) Q6.6(S) Q6.7(S) Q6.8(S) Q6.9(S) Q6.10(S) Q7.2(S) Q8.2(S) Q9.1(S) Q9.2(S) Q9.3(S) R7.1 R17.1 R18.1 U1.21(SOURCE)
N16359410: J1.9(EESDA) J2.12(AUXSDA) R13.2 U2.5(SDA)
N16362829: R14.2 TP2.1 U2.7(WP)
N16374572: D5.2(ANODE) Q3.3 R21.2
N16374891: D6.2(ANODE) Q4.3 R10.2
N16374930: D7.2(ANODE) Q5.3 R11.2
N18222437: R7.2 R8.1 U1.20(FB)
N18284784: JP5.2 JP5.3 U1.11(ADR2)
N18289049: JP4.2 JP4.3 U1.10(ADR1)
N18292359: JP3.2 JP3.3 U1.9(ADR0)
N18306085: JP6.2 U1.4(WP)
N18368024: C4.1 E7.1(A) JP2.2 JP2.3 R9.2 U1.1(ON)
N18459479: C3.1 JP1.1 U1.8(CLKIN) Y1.1 Y2.1
N18461854: C2.1 U1.7(CLKOUT) Y1.2 Y2.3
N18667288: J1.11(EESCL) J2.11(AUXSCL) R12.2 U2.6(SCL)
N18704667: E12.1(A) Q3.1 R22.2 R25.2 R26.2 U1.15(~{ALERT})
N18712255: C11.1 E19.1(A) R1.2 R2.1 U1.28(UV)
N18712591: E20.1(A) R2.2 R3.1 U1.2(OV)
N18750723: C7.1 E18.1(A) U1.6(TIMER)
N19150519: E13.1(A) R16.2
N19152397: E14.1(A) R15.2
N20179784: R37.1 R38.2 SKT1.23(ADC-) SKT1.24(SENSE-) SKT1.25(SENSE+) SKT1.26(ADC+) SKT1.27(VDD)
N20179796: R33.1 R36.2 SKT1.11(ADR2)
N20179824: R31.1 R34.2 SKT1.9(ADR0)
N20179836: R32.1 R35.2 SKT1.10(ADR1)
N20179848: C5.1 R34.1 R35.1 R36.1 SKT1.5(INTVCC)
N20179946: D4.2(ANODE) R37.2
N20972803: J2.7(GPIO_1) R24.1
N20976156: J2.9(OUTEN_1) R23.1
N21012841: D3.2(ANODE) R17.2 Z1.1(C)
N21043579: D9.2(ANODE) R4.1 Z2.1(C)
N21809093: D8.2(ANODE) R6.2 Z3.1(C)
N22593523: Q7.1(G) R73.1
N22593581: C12.2 R76.1
N22881125: D1.2(ANODE) R5.2
N22886736: D2.2(ANODE) R18.2
N23238552: R56.1 R57.2 R59.1
N23238556: R50.2 R52.1 R53.2
N23238564: R55.2 R57.1 R58.2
N23238578: R65.2 R67.1 R68.2
N23238583: R71.1 R72.2 R75.1
N23238612: R60.2 R62.1 R63.2
N23238895: R51.1 R52.2 R54.1
N23238977: R66.1 R67.2 R69.1
N23239010: R70.2 R72.1 R74.2
N23239014: R61.1 R62.2 R64.1
N23716100: Q1.1(G) R29.1
N23716105: Q2.1(G) R30.1
N23747318: J1.14(GPIO) R26.1
N23747809: J2.6(ALERTB) R25.1
N23797330: Q9.4(G) R39.2
N23797369: Q6.1(G) R28.2
N23797381: Q8.1(G) R27.2
N23797446: R41.1 R46.1 R79.1 R84.2 R86.1 R91.1
N23797523: R43.2 R48.2 R81.2 R88.2 R93.2 R95.1
N23797555: R85.1 R87.2 R88.1
N23797559: R91.2 R92.1 R94.2
N23797573: R86.2 R87.1 R89.2
N23797585: R46.2 R47.1 R77.2
N23797587: R40.1 R42.2 R43.1
N23797617: R79.2 R80.1 R82.2
N23797736: R44.1 R49.2 R77.1 R82.1 R89.1 R94.1
N23797774: R40.2 R45.2 R78.2 R83.1 R85.2 R90.2
N23797895: R90.1 R92.2 R93.1
N23797982: R45.1 R47.2 R48.1
N23798015: R41.2 R42.1 R44.2
N23798019: R78.1 R80.2 R81.1

Not connected (* = marked no-connect by the designer): J1 1(VUNREG)* 5(MISO)* 6(CS)*; J2 8(OUTEN_0); JP1 3*; SKT1 1(ON)* 2(OV)* 6(TIMER)* 7(CLKOUT)* 15(~{ALERT})* 16(GPIO3)* 17(GPIO2)* 18(GPIO1)* 20(FB)* 21(SOURCE)* 22(GATE)* 28(UV)*

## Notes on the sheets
sheet 1
- PCA ADDITIONAL PARTS
- HIGH CURRENT HOT SWAP CONTROLLER
- WITH I2C COMPATIBLE MONITORING AND EEPROM
- Tuesday, May 10, 2016
sheet 2
- +12V IN
- CONNECTIONS TO PAGES 2 AND 3
- +12V IN
- = HIGH-CURRENT CONNECTIONS
- +12V OUT
- +12V OUT
- 50 AMPS
- GPIO3
- GPIO2
- IN
- ON
- INTVCC
- ON
- (300K)
- OUT
- (SHORT PIN)
- OV
- UV
- FLOAT
- GPIO1
- (0.1u)
- GND
- GND
- GPI01
- SDA
- GPI02
- SCL
- OPT
- CLK
- GPI03
- INT
- ALERT
- EXT
- INT VCC
- EXT 5V
- TIMER
- GND
- GND
- ADR2
- ADR1
- ADR0
- WRITE PROTECT
- GND
- H
- H
- Quik Eval
- TM
- LOCK
- UNLESS OTHERWISE NOTED:
- NC
- NC
- WRITE
- 1. ALL RESISTORS THIS PAGE ARE 1% 0603.
- L
- L
- 2. ALL CAPACITORS THIS PAGE ARE 0603.
- SCL
- GND
- ALERT
- SCL
- SDA
- ASSEMBLY OPTIONS
- LTC SKU#
- SKT 1 ( PAGE 3 )
- DC2278A-A
- NOT STUFFED
- DC2278A-B
- STUFFED
- DC 1613
- HIGH CURRENT HOT SWAP CONTROLLER
- WITH I2C COMPATIBLE MONITORING AND EEPROM
- Tuesday, May 10, 2016
sheet 3
- "RS2"
- PRIMARY SIDE
- 1000 uF
- ADC-
- NICHICON P/N UVR1E102MPD
- SENSE+
- (OPT)
- OR EQUIVALENT
- "Q2"
- ADC+
- SENSE-
- PRIMARY SIDE
- 1000 uF
- (OPT)
- NICHICON P/N UVR1E102MPD
- (TO BOTTOM SIDE)
- OR EQUIVALENT
- GATE
- (OPT)
- (OPT)
- "Q2"
- SECONDARY SIDE
- (OPT)
- (FROM TOP SIDE)
- =HIGH CURRENT CONNECTIONS
- UNLESS OTHERWISE NOTED:
- 1. ALL RESISTORS THIS PAGE ARE 1% 0402.
- HIGH CURRENT HOT SWAP CONTROLLER
- OPT
- OPT
- WITH I2C COMPATIBLE MONITORING AND EEPROM
- 2. ALL CAPACITORS THIS PAGE ARE 0603.
- 3. ALL 0.003 OHM SENSE RESISTORS ARE SIZE 2512.
- Tuesday, May 10, 2016
sheet 4
- OPTIONAL PROGRAMMING SOCKET,
- INSTALLED ON -B ASSEMBLY OPTION
- SOCKET POWER
- SOCKET
- POWER
- 0N
- UNLESS OTHERWISE NOTED:
- 1. ALL RESISTORS THIS PAGE ARE 0603.
- HIGH CURRENT HOT SWAP CONTROLLER
- WITH I2C COMPATIBLE MONITORING AND EEPROM
- Tuesday, May 10, 2016
- WITH I2C COMPATIBLE MONITORING AND EEPROM
- 4-03-2013
